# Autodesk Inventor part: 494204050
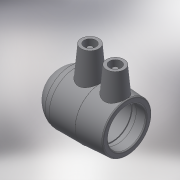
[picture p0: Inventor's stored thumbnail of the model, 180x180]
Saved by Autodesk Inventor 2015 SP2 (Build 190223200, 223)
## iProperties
Created: 2017-06
Part Number: 494204050
Material: Generic
Description: PLASSON END CAP MONOLITHIC 50
Document SubType Name: Modeling
Designer: Кирилл
Density: 1 g/cm^3
Appearance: Default
Author: Кирилл
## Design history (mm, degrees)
derived "494204.ipt"
feature "Solid1::494204.ipt"
tag "TaggingFeature1"
body "Solid1"
other parameters: "d0" = 82, "d1" = 1, "d2" = 55, "d4" = 68, "d5" = 8.2, "d7" = 2.04, "d8" = 28.7, "d10" = 1.36, "d11" = 16.4, "d12" = 168 deg, "d13" = 5.46667, "d15" = 56, "d16" = 15, "d17" = 41, "d18" = 1, "d20" = 5 deg, "d21" = 50.4, "d22" = 15, "d23" = 1, "d24" = 68.88, "d26" = 5 deg, "d27" = 4, "d29" = 14, "d30" = 0, "d31" = 4, "d33" = 14, "d34" = 0, "d37" = 45, "d38" = 55, "d39" = 63.25, "d40" = 54.4, "d41" = 2.5, "d42" = 0, "d44" = 360 deg, "d46" = 3, "d47" = 0, "d48" = 3, "d49" = 0, "L_" = 82, "L_1" = 55, "D_" = 68, "A_" = 56, "d_2" = 12
